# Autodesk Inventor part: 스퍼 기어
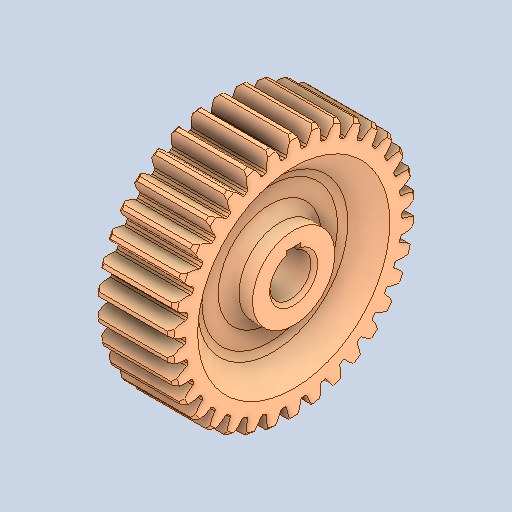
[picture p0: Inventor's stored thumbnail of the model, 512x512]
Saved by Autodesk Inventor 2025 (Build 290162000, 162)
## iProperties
Created: 2026-03
Part Number: 스퍼 기어
Material: 강철, 합금
Document SubType Name: Modeling
Designer: KDI
Density: 7.73 g/cm^3
Appearance: 기본값
Author: jhkim
Sending System: Autodesk Inventor 2026
Preprocessor: ST-DEVELOPER v20.1
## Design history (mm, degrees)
feature "솔리드1"
node "솔리드2"
